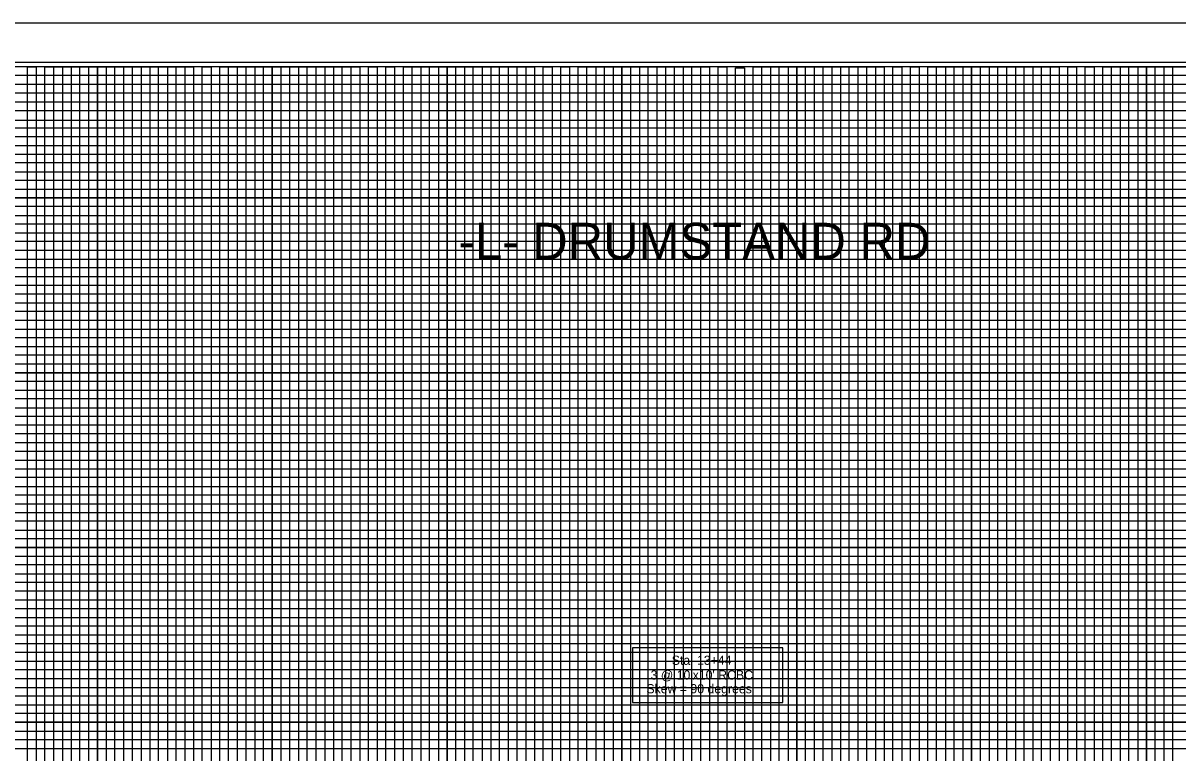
# Model space of a CAD drawing. Extents: x 573624 to 575507, y -53727 to -52273.
# Drawn here: x 574148 to 574809, y -52691 to -52273 of the extents above; entities that cross this region are included whole.
import ezdxf

# ---------------------------------------------------------------- set-up
doc = ezdxf.new("R2010")
doc.units = 0
for name, color, linetype in [('Prop Grid Mask', 7, 'Continuous'), ('Sheet Cutting Line CELL', 7, 'Continuous'), ('Sheet DOT Grid CELL', 7, 'Continuous'), ('Sheet Layout Profile Border', 7, 'Continuous'), ('Sheet Plot Border Inside CELL', 7, 'Continuous'), ('Sheet Plot Border Outside CELL', 7, 'Continuous'), ('Sheet Profile CELL', 7, 'Continuous'), ('Sheet Profile Grid Major CELL', 7, 'Continuous'), ('Sheet Profile Grid Middle CELL', 7, 'Continuous'), ('Sheet Profile Grid Minor CELL', 7, 'Continuous')]:
    doc.layers.add(name, color=color, linetype=linetype)

msp = doc.modelspace()

# ---------------------------------------------------------------- linework, layer by layer
at = {"layer": 'Prop Grid Mask'}
msp.add_lwpolyline([(574496.81, -52661.83), (574582.84, -52661.83), (574582.84, -52630.44), (574496.81, -52630.44)], close=True, dxfattribs=at)
at = {"layer": 'Sheet Cutting Line CELL'}
msp.add_line((575307.78, -52273.09), (573623.78, -52273.09), dxfattribs=at)
at = {"layer": 'Sheet DOT Grid CELL'}
for p, q in [((574190.78, -52298.09), (574190.78, -53323.09)), ((574240.78, -52298.09), (574240.78, -53323.09)), ((574290.78, -52298.09), (574290.78, -53323.09)), ((574340.78, -52298.09), (574340.78, -53323.09)), ((574390.78, -52298.09), (574390.78, -53323.09)), ((574440.78, -52298.09), (574440.78, -53323.09)), ((574490.78, -52298.09), (574490.78, -53323.09)), ((574540.78, -52298.09), (574540.78, -53323.09)), ((574590.78, -52298.09), (574590.78, -53323.09)), ((574640.78, -52298.09), (574640.78, -53323.09)), ((574690.78, -52298.09), (574690.78, -53323.09)), ((574740.78, -52298.09), (574740.78, -53323.09)), ((574790.78, -52298.09), (574790.78, -53323.09)), ((573790.78, -52323.09), (575090.73, -52323.09)), ((573790.78, -52373.09), (575090.73, -52373.09)), ((573790.78, -52423.09), (575090.73, -52423.09)), ((573790.78, -52473.09), (575290.78, -52473.09)), ((573790.78, -52523.09), (575290.78, -52523.09)), ((573790.78, -52573.09), (575290.78, -52573.09)), ((573790.78, -52623.09), (575290.78, -52623.09)), ((573790.78, -52673.09), (575290.78, -52673.09))]:
    msp.add_line(p, q, dxfattribs=at)
at = {"layer": 'Sheet Layout Profile Border'}
msp.add_lwpolyline([(573840.78, -52298.09), (573840.78, -53323.09), (575240.78, -53323.09), (575240.78, -52435.64), (575090.73, -52435.64), (575090.73, -52298.09)], close=True, dxfattribs=at)
at = {"layer": 'Sheet Plot Border Inside CELL'}
msp.add_lwpolyline([(575303.28, -52295.54), (573636.78, -52295.54), (573636.78, -53350.64), (575303.28, -53350.64)], close=True, dxfattribs=at)
at = {"layer": 'Sheet Plot Border Outside CELL'}
msp.add_lwpolyline([(575307.78, -52273.09), (573623.78, -52273.09), (573623.78, -53373.09), (575307.78, -53373.09)], close=True, dxfattribs=at)
at = {"layer": 'Sheet Profile CELL'}
msp.add_lwpolyline([(575290.78, -52298.09), (573790.78, -52298.09), (573790.78, -53348.09), (575290.78, -53348.09)], close=True, dxfattribs=at)
at = {"layer": 'Sheet Profile Grid Major CELL'}
for points in [[(574190.78, -53323.09), (574190.78, -52298.09), (574240.78, -52298.09), (574240.78, -53323.09)], [(574290.78, -53323.09), (574290.78, -52298.09), (574340.78, -52298.09), (574340.78, -53323.09)], [(574390.78, -53323.09), (574390.78, -52298.09), (574440.78, -52298.09), (574440.78, -53323.09)], [(574490.78, -53323.09), (574490.78, -52298.09), (574540.78, -52298.09), (574540.78, -53323.09)], [(574590.78, -53323.09), (574590.78, -52298.09), (574640.78, -52298.09), (574640.78, -53323.09)], [(574690.78, -53323.09), (574690.78, -52298.09), (574740.78, -52298.09), (574740.78, -53323.09)], [(574790.78, -53323.09), (574790.78, -52298.09), (574840.78, -52298.09)], [(575090.73, -52373.09), (573790.88, -52373.09), (573790.88, -52323.14), (575090.73, -52323.14)], [(575290.78, -52473.09), (573790.78, -52473.09), (573790.78, -52423.09), (575090.73, -52423.09)], [(575290.78, -52573.09), (573790.78, -52573.09), (573790.78, -52523.09), (575290.78, -52523.09)], [(575290.78, -52673.09), (573790.78, -52673.09), (573790.78, -52623.09), (575290.78, -52623.09)]]:
    msp.add_lwpolyline(points, dxfattribs=at)
at = {"layer": 'Sheet Profile Grid Middle CELL'}
for points in [[(574165.78, -53323.09), (574165.78, -52298.09), (574215.78, -52298.09), (574215.78, -53323.09)], [(574265.78, -53323.09), (574265.78, -52298.09), (574315.78, -52298.09), (574315.78, -53323.09)], [(574365.78, -53323.09), (574365.78, -52298.09), (574415.78, -52298.09), (574415.78, -53323.09)], [(574465.78, -53323.09), (574465.78, -52298.09), (574515.78, -52298.09), (574515.78, -53323.09)], [(574565.78, -53323.09), (574565.78, -52298.09), (574615.78, -52298.09), (574615.78, -53323.09)], [(574665.78, -53323.09), (574665.78, -52298.09), (574715.78, -52298.09), (574715.78, -53323.09)], [(574765.78, -53323.09), (574765.78, -52298.09), (574815.78, -52298.09)], [(573790.78, -52348.09), (575090.73, -52348.09)], [(575090.73, -52398.09), (573790.78, -52398.09), (573790.78, -52448.14), (575290.78, -52448.14)], [(575290.78, -52498.09), (573790.78, -52498.09), (573790.78, -52548.09), (575290.78, -52548.09)], [(575290.78, -52598.09), (573790.78, -52598.09), (573790.78, -52648.09), (575290.78, -52648.09)]]:
    msp.add_lwpolyline(points, dxfattribs=at)
at = {"layer": 'Sheet Profile Grid Minor CELL'}
for p, q in [((575240.78, -52478.09), (573840.78, -52478.09)), ((573840.78, -52483.09), (575240.78, -52483.09)), ((575240.78, -52503.09), (573840.78, -52503.09))]:
    msp.add_line(p, q, dxfattribs=at)
for points in [[(575090.73, -52303.09), (573840.78, -52303.09), (573840.78, -52308.09), (575090.73, -52308.09)], [(574150.78, -53323.09), (574150.78, -52298.09), (574155.78, -52298.09), (574155.78, -53323.09)], [(574160.78, -53323.09), (574160.78, -52298.09), (574170.78, -52298.09), (574170.78, -53323.09)], [(574175.78, -52298.09), (574175.78, -53323.09), (574180.78, -53323.09), (574180.78, -52298.09)], [(574175.78, -52298.69), (574175.78, -53323.09), (574180.78, -53323.09), (574180.78, -52298.69)], [(574185.78, -53323.09), (574185.78, -52298.09), (574195.78, -52298.09), (574195.78, -53323.09)], [(574200.78, -53323.09), (574200.78, -52298.09), (574205.78, -52298.09), (574205.78, -53323.09)], [(574210.78, -53323.09), (574210.78, -52298.09), (574220.78, -52298.09), (574220.78, -53323.09)], [(574225.78, -53323.09), (574225.78, -52298.09), (574230.78, -52298.09), (574230.78, -53323.09)], [(574235.78, -53323.09), (574235.78, -52298.09), (574245.78, -52298.09), (574245.78, -53323.09)], [(574250.78, -53323.09), (574250.78, -52298.09), (574255.78, -52298.09), (574255.78, -53323.09)], [(574260.78, -53323.09), (574260.78, -52298.09), (574270.78, -52298.09), (574270.78, -53323.09)], [(574275.78, -53323.09), (574275.78, -52298.09), (574280.78, -52298.09), (574280.78, -53323.09)], [(574285.78, -53323.09), (574285.78, -52298.09), (574295.78, -52298.09), (574295.78, -53323.09)], [(574300.78, -53323.09), (574300.78, -52298.09), (574305.78, -52298.09), (574305.78, -53323.09)], [(574310.78, -53323.09), (574310.78, -52298.09), (574320.78, -52298.09), (574320.78, -53323.09)], [(574325.78, -52298.09), (574325.78, -53323.09), (574330.78, -53323.09), (574330.78, -52298.09), (574335.78, -52298.09), (574335.78, -53323.09), (574345.78, -53323.09), (574345.78, -52298.09), (574350.78, -52298.09), (574350.78, -53323.09), (574355.78, -53323.09), (574355.78, -52298.09), (574360.78, -52298.09), (574360.78, -53323.09)], [(574370.78, -53323.09), (574370.78, -52298.09), (574375.78, -52298.09), (574375.78, -53323.09)], [(574380.78, -53323.09), (574380.78, -52298.09), (574385.78, -52298.09), (574385.78, -53323.09)], [(574395.78, -53323.09), (574395.78, -52298.09), (574400.78, -52298.09), (574400.78, -53323.09)], [(574405.78, -53323.09), (574405.78, -52298.09), (574410.78, -52298.09), (574410.78, -53323.09)], [(574420.78, -53323.09), (574420.78, -52298.09), (574425.78, -52298.09), (574425.78, -53323.09)], [(574430.78, -53323.09), (574430.78, -52298.09), (574435.78, -52298.09), (574435.78, -53323.09)], [(574445.78, -53323.09), (574445.78, -52298.09), (574450.78, -52298.09), (574450.78, -53323.09)], [(574455.78, -53323.09), (574455.78, -52298.09), (574460.78, -52298.09), (574460.78, -53323.09)], [(574470.78, -53323.09), (574470.78, -52298.09), (574475.78, -52298.09), (574475.78, -53323.09)], [(574480.78, -53323.09), (574480.78, -52298.09), (574485.78, -52298.09), (574485.78, -53323.09)], [(574495.78, -53323.09), (574495.78, -52298.09), (574500.78, -52298.09), (574500.78, -53323.09)], [(574505.78, -53323.09), (574505.78, -52298.09), (574510.78, -52298.09), (574510.78, -53323.09)], [(574520.78, -53323.09), (574520.78, -52298.09), (574525.78, -52298.09), (574525.78, -53323.09)], [(574530.78, -53323.09), (574530.78, -52298.09), (574535.78, -52298.09), (574535.78, -53323.09)], [(574545.78, -53323.09), (574545.78, -52298.09), (574550.78, -52298.09), (574550.78, -53323.09)], [(574555.78, -53323.09), (574555.78, -52298.69), (574560.78, -52298.69), (574560.78, -53323.09)], [(574570.78, -53323.09), (574570.78, -52298.09), (574575.78, -52298.09), (574575.78, -53323.09)], [(574580.78, -53323.09), (574580.78, -52298.09), (574585.78, -52298.09), (574585.78, -53323.09)], [(574595.78, -53323.09), (574595.78, -52298.09), (574600.78, -52298.09), (574600.78, -53323.09)], [(574605.78, -53323.09), (574605.78, -52298.09), (574610.78, -52298.09), (574610.78, -53323.09)], [(574620.78, -53323.09), (574620.78, -52298.09), (574625.78, -52298.09), (574625.78, -53323.09)], [(574630.78, -53323.09), (574630.78, -52298.09), (574635.78, -52298.09), (574635.78, -53323.09)], [(574645.78, -53323.09), (574645.78, -52298.09), (574650.78, -52298.09), (574650.78, -53323.09)], [(574655.78, -53323.09), (574655.78, -52298.09), (574660.78, -52298.09), (574660.78, -53323.09)], [(574670.78, -53323.09), (574670.78, -52298.09), (574675.78, -52298.09), (574675.78, -53323.09)], [(574680.78, -53323.09), (574680.78, -52298.09), (574685.78, -52298.09), (574685.78, -53323.09)], [(574695.78, -53323.09), (574695.78, -52298.09), (574700.78, -52298.09), (574700.78, -53323.09)], [(574705.78, -53323.09), (574705.78, -52298.09), (574710.78, -52298.09), (574710.78, -53323.09)], [(574720.78, -53323.09), (574720.78, -52298.09), (574725.78, -52298.09), (574725.78, -53323.09)], [(574730.78, -53323.09), (574730.78, -52298.09), (574735.78, -52298.09), (574735.78, -53323.09)], [(574745.78, -53323.09), (574745.78, -52298.09), (574750.78, -52298.09), (574750.78, -53323.09)], [(574755.78, -53323.09), (574755.78, -52298.09), (574760.78, -52298.09), (574760.78, -53323.09)], [(574770.78, -53323.09), (574770.78, -52298.09), (574775.78, -52298.09), (574775.78, -53323.09)], [(574780.78, -53323.09), (574780.78, -52298.09), (574785.78, -52298.09), (574785.78, -53323.09)], [(574795.78, -53323.09), (574795.78, -52298.09), (574800.78, -52298.09), (574800.78, -53323.09)], [(574805.78, -53323.09), (574805.78, -52298.09), (574810.78, -52298.09)], [(575090.73, -52313.09), (573840.78, -52313.09), (573840.78, -52318.09), (575090.73, -52318.09)], [(575090.73, -52328.84), (573841.78, -52328.84), (573841.78, -52333.09), (575090.73, -52333.09)], [(575090.73, -52338.09), (573840.78, -52338.09), (573840.78, -52343.09), (575090.73, -52343.09)], [(575090.73, -52353.09), (573840.78, -52353.09), (573840.78, -52358.09), (575090.73, -52358.09)], [(575090.73, -52363.09), (573840.78, -52363.09), (573840.78, -52368.09), (575090.73, -52368.09)], [(575090.73, -52378.09), (573840.78, -52378.09), (573840.78, -52383.09), (575090.73, -52383.09)], [(575090.73, -52388.09), (573840.78, -52388.09), (573840.78, -52393.09), (575090.73, -52393.09)], [(575090.73, -52403.09), (573840.78, -52403.09), (573840.78, -52408.09), (575090.73, -52408.09)], [(575090.73, -52413.09), (573840.78, -52413.09), (573840.78, -52418.09), (575090.73, -52418.09)], [(575090.73, -52428.09), (573840.78, -52428.09), (573840.78, -52433.09), (575090.73, -52433.09)], [(575240.78, -52438.09), (573840.78, -52438.09), (573840.78, -52438.09), (573840.78, -52458.09), (575240.78, -52458.09)], [(573840.78, -52443.09), (575240.78, -52443.09)], [(575240.78, -52453.09), (573840.78, -52453.09)], [(575240.78, -52463.09), (573840.78, -52463.09), (573840.78, -52468.09), (575240.78, -52468.09)], [(575240.78, -52488.09), (573840.78, -52488.09), (573840.78, -52493.09), (575240.78, -52493.09)], [(575240.78, -52508.09), (573840.78, -52508.09), (573840.78, -52513.09), (575240.78, -52513.09)], [(575240.78, -52518.09), (573840.78, -52518.09)], [(573840.78, -52528.09), (575240.78, -52528.09)], [(575240.78, -52533.09), (573840.78, -52533.09), (573840.78, -52538.09), (575240.78, -52538.09)], [(575240.78, -52543.09), (573840.78, -52543.09), (573840.78, -52553.09), (575240.78, -52553.09)], [(575240.78, -52558.09), (573840.78, -52558.09), (573840.78, -52563.09), (575240.78, -52563.09)], [(575240.78, -52568.09), (573840.78, -52568.09), (573840.78, -52578.09), (575240.78, -52578.09)], [(575240.78, -52583.09), (573840.78, -52583.09), (573840.78, -52588.09), (575240.78, -52588.09)], [(575240.78, -52593.09), (573840.78, -52593.09), (573840.78, -52603.09), (575240.78, -52603.09)], [(575240.78, -52608.09), (573840.78, -52608.09), (573840.78, -52613.09), (575240.78, -52613.09)], [(575240.78, -52618.09), (573840.78, -52618.09), (573840.78, -52628.09), (575240.78, -52628.09)], [(575240.78, -52633.09), (573840.78, -52633.09), (573840.78, -52638.09), (575240.78, -52638.09)], [(575240.78, -52643.09), (573840.78, -52643.09), (573840.78, -52653.09), (575240.78, -52653.09)], [(575240.78, -52658.09), (573840.78, -52658.09), (573840.78, -52663.09), (575240.78, -52663.09)], [(575240.78, -52668.09), (573840.78, -52668.09), (573840.78, -52678.09), (575240.78, -52678.09)], [(575240.78, -52683.09), (573840.78, -52683.09), (573840.78, -52688.09), (575240.78, -52688.09)]]:
    msp.add_lwpolyline(points, dxfattribs=at)

# ---------------------------------------------------------------- texts
at = {"layer": 'Prop Grid Mask'}
for s, height, p in [('-L- DRUMSTAND RD', 21, (574397.34, -52408.32)), ('Sta. 13+44', 5.25, (574519.28, -52640.19)), ("3 @ 10'x10' RCBC", 5.25, (574507.15, -52648.64)), ('Skew = 90 degrees', 5.25, (574504.78, -52656.49))]:
    msp.add_text(s, height=height, dxfattribs=at).set_placement(p)

doc.saveas('drawing.dxf')
